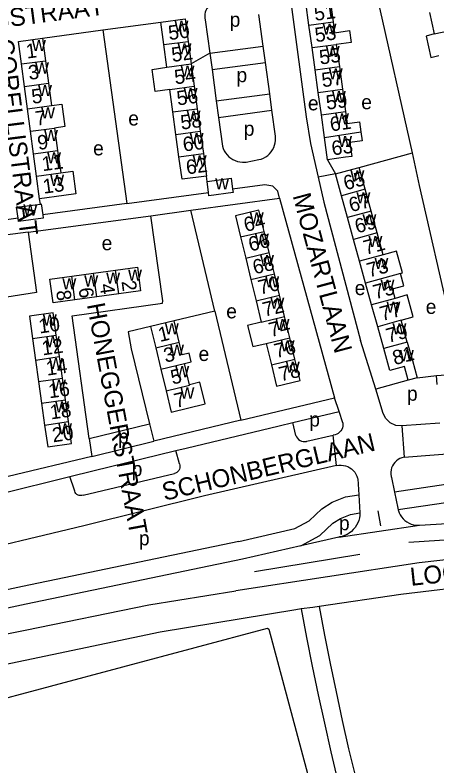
# Model space of a CAD drawing. Extents: x 159045 to 160918, y 380454 to 382516.
# Drawn here: x 159624.4 to 159741.6, y 380775.4 to 380983.9 of the extents above; entities that cross this region are included whole.
import ezdxf

# ---------------------------------------------------------------- set-up
doc = ezdxf.new("R2010")
doc.units = 0
for name, color, linetype in [('BLT_Basislijn', 7, 'Continuous'), ('BLT_Bebouwing', 7, 'Continuous'), ('BLT_Centroide', 7, 'Continuous'), ('BLT_Huisnummer', 7, 'Continuous'), ('BLT_Huisnummer_ tussenligend', 7, 'Continuous'), ('BLT_Onderverdeling_panden', 7, 'Continuous'), ('BLT_Straatnaam', 7, 'Continuous'), ('BLT_Vlakafsluiter', 7, 'Continuous')]:
    doc.layers.add(name, color=color, linetype=linetype)

msp = doc.modelspace()

# ---------------------------------------------------------------- linework, layer by layer
at = {"layer": 'BLT_Basislijn'}
for p, q in [((159734.78, 380945.62), (159724.83, 380989.95)), ((159677.16, 380983.06), (159677.26, 380982.6)), ((159677.26, 380982.6), (159678.52, 380973.28)), ((159693.34, 380975.29), (159692.16, 380984.04)), ((159648.82, 380979.77), (159664.91, 380981.9)), ((159632.05, 380977.44), (159648.82, 380979.77)), ((159648.82, 380979.77), (159655.51, 380931.55)), ((159678.52, 380973.28), (159693.34, 380975.29)), ((159693.96, 380970.71), (159693.34, 380975.29)), ((159678.52, 380973.28), (159679.13, 380968.73)), ((159679.13, 380968.73), (159693.96, 380970.71)), ((159695.14, 380962.01), (159693.96, 380970.71)), ((159679.13, 380968.73), (159680.31, 380960.03)), ((159680.31, 380960.03), (159695.14, 380962.01)), ((159695.76, 380957.46), (159695.14, 380962.01)), ((159680.31, 380960.03), (159680.92, 380955.46)), ((159680.92, 380955.46), (159695.76, 380957.46)), ((159696.74, 380950.23), (159695.76, 380957.46)), ((159680.92, 380955.46), (159682, 380947.49)), ((159720, 380941.58), (159734.78, 380945.62)), ((159688.58, 380943.07), (159692.12, 380943.74)), ((159711.21, 380943.7), (159713.44, 380939.77)), ((159677.73, 380937.68), (159677.55, 380939.2)), ((159713.44, 380939.77), (159708.58, 380938.84)), ((159655.51, 380931.55), (159678.14, 380934.62)), ((159631.45, 380931.41), (159631.25, 380932.91)), ((159673.28, 380929.68), (159697.9, 380933.09)), ((159697.9, 380933.09), (159713.14, 380877.64)), ((159655.51, 380931.55), (159632.11, 380928.38)), ((159662.16, 380928.16), (159673.28, 380929.68)), ((159679.91, 380901.66), (159673.28, 380929.68)), ((159625.26, 380927.46), (159612.94, 380925.8)), ((159628.06, 380923.63), (159662.16, 380928.16)), ((159628.06, 380923.63), (159599.52, 380919.83)), ((159679.91, 380901.66), (159668.57, 380899.01)), ((159679.91, 380901.66), (159687.1, 380871.43)), ((159724.57, 380879.99), (159720.34, 380893.51)), ((159733.63, 380882.49), (159724.57, 380879.99)), ((159736.08, 380883.17), (159741.42, 380883.85)), ((159726.66, 380873.3), (159724.57, 380879.99)), ((159687.1, 380871.43), (159713.14, 380877.64)), ((159714.4, 380873.83), (159713.14, 380877.64)), ((159701.52, 380870.76), (159714.4, 380873.83)), ((159715.44, 380870.7), (159714.4, 380873.83)), ((159645.03, 380866.31), (159661.78, 380870.42)), ((159661.78, 380870.42), (159662.96, 380865.57)), ((159687.1, 380871.43), (159662.96, 380865.57)), ((159702.39, 380867.16), (159701.52, 380870.76)), ((159742.35, 380870.62), (159731.82, 380869.8)), ((159645.03, 380866.31), (159645.71, 380861.33)), ((159705.48, 380865.55), (159712.8, 380867.27)), ((159645.71, 380861.33), (159662.96, 380865.57)), ((159670.06, 380859.28), (159669.06, 380862.95)), ((159645.71, 380861.33), (159622.53, 380855.79)), ((159640.96, 380852), (159639.62, 380855.76)), ((159643.32, 380850.61), (159668.66, 380856.63)), ((159728.94, 380855.47), (159729.78, 380851.4)), ((159719.6, 380855.12), (159719.88, 380850.69)), ((159729.78, 380851.4), (159730.69, 380847.02)), ((159719.88, 380850.69), (159720.19, 380845.67)), ((159725.19, 380846.25), (159725.88, 380842.09)), ((159630.36, 380838.96), (159596.82, 380830.73)), ((159714.32, 380838.96), (159703.75, 380836.52)), ((159733.79, 380837.57), (159763.63, 380839.43)), ((159703.75, 380836.52), (159687.61, 380832.79)), ((159690.9, 380829.36), (159720.18, 380834.21)), ((159703.92, 380818.98), (159702.38, 380818.76)), ((159707.16, 380819.44), (159703.92, 380818.98)), ((159708.87, 380819.68), (159707.16, 380819.44))]:
    msp.add_line(p, q, dxfattribs=at)
for points in [[(159679.86, 380987.36), (159679.34, 380987.16), (159678.85, 380986.88), (159678.41, 380986.54), (159678.02, 380986.14), (159677.7, 380985.69), (159677.44, 380985.2), (159677.25, 380984.68), (159677.15, 380984.13), (159677.12, 380983.58), (159677.16, 380983.06)], [(159705.16, 380987.36), (159701.3, 380987.08), (159701.09, 380986.78), (159705.25, 380955.64), (159706.44, 380948.27), (159708.58, 380938.84)], [(159692.12, 380943.74), (159692.78, 380943.92), (159693.42, 380944.18), (159694.02, 380944.52), (159694.58, 380944.92), (159695.09, 380945.39), (159695.54, 380945.91), (159695.93, 380946.47), (159696.25, 380947.08), (159696.5, 380947.73), (159696.67, 380948.39), (159696.76, 380949.08), (159696.78, 380949.77), (159696.74, 380950.23)], [(159682, 380947.49), (159682.22, 380946.83), (159682.51, 380946.2), (159682.87, 380945.61), (159683.3, 380945.06), (159683.79, 380944.57), (159684.33, 380944.13), (159684.92, 380943.77), (159685.55, 380943.47), (159686.21, 380943.24), (159686.88, 380943.1), (159687.58, 380943.03), (159688.27, 380943.04), (159688.58, 380943.07)], [(159757.79, 380900.82), (159746.59, 380898.96), (159745.36, 380898.99), (159736.77, 380936.61), (159734.78, 380945.62)], [(159708.58, 380938.84), (159710.15, 380931.92), (159720.34, 380893.51)], [(159697.9, 380933.09), (159697.38, 380934.95), (159696, 380936.42), (159693.83, 380936.74), (159684.83, 380935.52)], [(159645.03, 380866.31), (159640.33, 380900.36), (159665.35, 380903.89), (159665.46, 380904.55), (159662.16, 380928.16)], [(159628.06, 380923.63), (159630.34, 380906.88), (159615.55, 380904.57), (159616.91, 380894.64)], [(159662.06, 380897.44), (159655.86, 380895.9), (159656.7, 380891.22), (159661.78, 380870.42)], [(159731.82, 380869.8), (159730.2, 380869.94), (159728.63, 380870.65), (159727.39, 380871.84), (159726.66, 380873.3)], [(159669.06, 380862.95), (159671.9, 380863.65), (159697.77, 380869.87), (159701.52, 380870.76)], [(159715.44, 380870.7), (159715.48, 380870.22), (159715.45, 380869.74), (159715.33, 380869.26), (159715.14, 380868.82), (159714.87, 380868.41), (159714.55, 380868.05), (159714.17, 380867.75), (159713.74, 380867.52), (159713.28, 380867.35), (159712.8, 380867.27)], [(159702.39, 380867.16), (159702.59, 380866.75), (159702.85, 380866.38), (159703.18, 380866.06), (159703.56, 380865.8), (159703.97, 380865.61), (159704.41, 380865.5), (159704.87, 380865.47), (159705.32, 380865.51), (159705.48, 380865.55)], [(159732.45, 380861.14), (159749.17, 380862.42), (159809.36, 380866.58)], [(159639.62, 380855.76), (159646.05, 380857.34), (159669.06, 380862.95)], [(159732.45, 380861.14), (159731.87, 380860.99), (159731.32, 380860.77), (159730.8, 380860.48), (159730.32, 380860.12), (159729.89, 380859.7), (159729.52, 380859.23), (159729.23, 380858.71), (159729, 380858.16), (159728.84, 380857.58), (159728.77, 380856.99), (159728.77, 380856.39), (159728.86, 380855.8), (159728.94, 380855.47)], [(159713.73, 380858.79), (159677.04, 380850.42), (159643.57, 380842.04), (159630.36, 380838.96)], [(159670.06, 380859.28), (159670.18, 380858.91), (159670.22, 380858.52), (159670.19, 380858.13), (159670.07, 380857.76), (159669.88, 380857.42), (159669.63, 380857.12), (159669.32, 380856.88), (159668.97, 380856.71), (159668.66, 380856.63)], [(159713.73, 380858.79), (159714.35, 380858.89), (159714.97, 380858.91), (159715.6, 380858.85), (159716.21, 380858.72), (159716.8, 380858.5), (159717.35, 380858.22), (159717.87, 380857.86), (159718.33, 380857.44), (159718.74, 380856.97), (159719.08, 380856.45), (159719.36, 380855.88), (159719.56, 380855.29), (159719.6, 380855.12)], [(159607.49, 380847.78), (159620.22, 380850.96), (159639.62, 380855.76)], [(159760.2, 380848.71), (159754.66, 380850.03), (159748.12, 380852.85), (159744.08, 380853.51), (159729.78, 380851.4)], [(159643.32, 380850.61), (159642.97, 380850.49), (159642.61, 380850.45), (159642.25, 380850.49), (159641.91, 380850.61), (159641.6, 380850.8), (159641.34, 380851.06), (159641.14, 380851.36), (159641.01, 380851.7), (159640.96, 380852)], [(159686.59, 380837.69), (159702.08, 380841.3), (159706.09, 380843.47), (159709.59, 380846.83), (159712.52, 380848.63), (159716.21, 380850.1), (159719.88, 380850.69)], [(159759.77, 380843.67), (159753.07, 380845.27), (159746.71, 380848.01), (159744.04, 380848.45), (159730.81, 380846.5)], [(159703.75, 380836.52), (159709.07, 380839.4), (159712.67, 380842.85), (159714.77, 380844.14), (159717.54, 380845.25), (159720.19, 380845.67)], [(159720.19, 380845.67), (159720.16, 380844.98), (159720.04, 380844.25), (159719.85, 380843.54), (159719.58, 380842.86), (159719.24, 380842.21), (159718.83, 380841.6), (159718.36, 380841.04), (159717.83, 380840.53), (159717.24, 380840.08), (159716.62, 380839.7), (159715.95, 380839.39), (159715.25, 380839.15), (159714.54, 380838.99), (159714.32, 380838.96)], [(159730.69, 380847.02), (159730.81, 380846.5)], [(159730.81, 380846.5), (159731.08, 380845.72), (159731.38, 380845.11), (159731.76, 380844.54), (159732.19, 380844.02), (159732.69, 380843.55), (159733.24, 380843.15), (159733.83, 380842.82), (159734.45, 380842.55), (159735.11, 380842.36), (159735.78, 380842.25), (159736.46, 380842.22), (159736.78, 380842.23)], [(159736.78, 380842.23), (159759.77, 380843.67)], [(159686.59, 380837.69), (159626.47, 380825.2), (159588, 380816.97)], [(159796.37, 380838.55), (159736.61, 380831.78), (159685.69, 380824.02)], [(159687.61, 380832.79), (159627.5, 380820.3), (159589.04, 380812.08)], [(159785.88, 380829.46), (159784.03, 380829.26), (159777.98, 380828.55), (159731.58, 380822.97), (159708.87, 380819.68)], [(159574.18, 380802.53), (159627.2, 380813.1), (159661.54, 380820.15), (159685.69, 380824.02)], [(159702.38, 380818.76), (159664.72, 380812.51), (159550.45, 380788.58)], [(159703.92, 380818.98), (159705.4, 380811.02), (159706.96, 380803.08), (159708.6, 380795.16), (159710.32, 380787.25), (159712.12, 380779.36), (159713.99, 380771.49), (159715.94, 380763.64), (159717.97, 380755.8), (159720.08, 380747.99), (159722.26, 380740.2), (159724.52, 380732.43), (159726.86, 380724.68), (159729.28, 380716.96), (159731.77, 380709.26), (159734.34, 380701.59), (159736.98, 380693.94), (159739.7, 380686.32), (159741.35, 380681.79)], [(159708.87, 380819.68), (159710.35, 380811.75), (159711.91, 380803.84), (159713.55, 380795.94), (159715.26, 380788.06), (159717.06, 380780.19), (159718.93, 380772.35), (159720.88, 380764.52), (159722.91, 380756.71), (159725.01, 380748.92), (159727.19, 380741.16), (159729.45, 380733.41), (159731.79, 380725.69), (159734.2, 380717.99), (159736.68, 380710.32), (159739.25, 380702.67), (159741.89, 380695.05), (159744.6, 380687.45), (159745.66, 380684.56)], [(159553.84, 380776.05), (159694.54, 380813.62), (159694.88, 380813.4), (159722.55, 380710.08), (159722.69, 380708.76), (159585.61, 380671.57)]]:
    msp.add_lwpolyline(points, dxfattribs=at)
at = {"layer": 'BLT_Bebouwing'}
for p, q in [((159706.03, 380981.12), (159705.16, 380987.36)), ((159739.52, 380984.62), (159740.83, 380978.64)), ((159665.75, 380975.67), (159664.91, 380981.9)), ((159706.89, 380974.88), (159706.03, 380981.12)), ((159632.05, 380977.44), (159632.89, 380971.21)), ((159672.51, 380976.58), (159673.35, 380970.35)), ((159666.59, 380969.44), (159665.75, 380975.67)), ((159707.76, 380968.65), (159706.89, 380974.88)), ((159627.04, 380964.07), (159626.2, 380970.31)), ((159632.89, 380971.21), (159633.73, 380964.98)), ((159673.35, 380970.35), (159674.19, 380964.12)), ((159708.62, 380962.41), (159707.76, 380968.65)), ((159714.49, 380969.58), (159715.36, 380963.34)), ((159627.88, 380957.84), (159627.04, 380964.07)), ((159633.73, 380964.98), (159634.57, 380958.74)), ((159674.19, 380964.12), (159675.03, 380957.89)), ((159668.27, 380956.98), (159667.43, 380963.21)), ((159709.49, 380956.17), (159708.62, 380962.41)), ((159715.36, 380963.34), (159716.22, 380957.11)), ((159628.72, 380951.61), (159627.88, 380957.84)), ((159675.03, 380957.89), (159675.87, 380951.66)), ((159669.11, 380950.75), (159668.27, 380956.98)), ((159710.35, 380949.93), (159709.49, 380956.17)), ((159629.56, 380945.37), (159628.72, 380951.61)), ((159635.41, 380952.51), (159636.25, 380946.28)), ((159675.87, 380951.66), (159676.71, 380945.43)), ((159669.95, 380944.52), (159669.11, 380950.75)), ((159711.21, 380943.7), (159710.35, 380949.93)), ((159630.4, 380939.14), (159629.56, 380945.37)), ((159636.25, 380946.28), (159637.1, 380940.04)), ((159676.71, 380945.43), (159677.55, 380939.2)), ((159721.67, 380935.51), (159720, 380941.58)), ((159631.25, 380932.91), (159630.4, 380939.14)), ((159715.11, 380933.71), (159713.44, 380939.77)), ((159678.14, 380934.62), (159677.73, 380937.68)), ((159723.34, 380929.45), (159721.67, 380935.51)), ((159716.77, 380927.64), (159715.11, 380933.71)), ((159725.01, 380923.39), (159723.34, 380929.45)), ((159718.44, 380921.58), (159716.77, 380927.64)), ((159687.06, 380922.27), (159688.49, 380916.35)), ((159695.01, 380917.92), (159693.58, 380923.84)), ((159726.68, 380917.33), (159725.01, 380923.39)), ((159720.11, 380915.52), (159718.44, 380921.58)), ((159688.49, 380916.35), (159689.92, 380910.43)), ((159696.43, 380912), (159695.01, 380917.92)), ((159721.78, 380909.46), (159720.11, 380915.52)), ((159640.16, 380911.4), (159646.24, 380912.23)), ((159646.24, 380912.23), (159652.32, 380913.05)), ((159697.86, 380906.09), (159696.43, 380912)), ((159689.92, 380910.43), (159691.35, 380904.51)), ((159723.45, 380903.4), (159721.78, 380909.46)), ((159647.13, 380905.63), (159641.05, 380904.8)), ((159653.22, 380906.45), (159647.13, 380905.63)), ((159699.29, 380900.17), (159697.86, 380906.09)), ((159641.05, 380904.8), (159634.97, 380903.98)), ((159691.35, 380904.51), (159692.77, 380898.59)), ((159725.12, 380897.34), (159723.45, 380903.4)), ((159635.89, 380895.03), (159635.03, 380901.17)), ((159700.72, 380894.25), (159699.29, 380900.17)), ((159668.57, 380899.01), (159662.06, 380897.44)), ((159662.06, 380897.44), (159663.5, 380891.49)), ((159670, 380893.06), (159668.57, 380899.01)), ((159726.79, 380891.27), (159725.12, 380897.34)), ((159733.35, 380893.08), (159731.68, 380899.14)), ((159636.73, 380889.05), (159635.89, 380895.03)), ((159702.15, 380888.33), (159700.72, 380894.25)), ((159663.5, 380891.49), (159664.94, 380885.54)), ((159694.2, 380892.67), (159695.63, 380886.76)), ((159728.46, 380885.21), (159726.79, 380891.27)), ((159637.58, 380883.07), (159636.73, 380889.05)), ((159630.11, 380888.11), (159630.95, 380882.13)), ((159672.86, 380881.24), (159671.44, 380887.11)), ((159664.94, 380885.54), (159666.37, 380879.59)), ((159638.43, 380877.03), (159637.58, 380883.07)), ((159630.95, 380882.13), (159631.8, 380876.1)), ((159639.28, 380871), (159638.43, 380877.03)), ((159631.8, 380876.1), (159632.65, 380870.06))]:
    msp.add_line(p, q, dxfattribs=at)
for points in [[(159711.9, 380988.29), (159712.59, 380983.34), (159712.76, 380982.05)], [(159664.91, 380981.9), (159671.67, 380982.82), (159672.51, 380976.58)], [(159712.76, 380982.05), (159713.17, 380979), (159717.27, 380979.57), (159717.73, 380976.31), (159713.64, 380975.75)], [(159740.83, 380978.64), (159738.61, 380978.05), (159739.9, 380972.08), (159742.13, 380972.65)], [(159626.2, 380970.31), (159625.36, 380976.54), (159632.05, 380977.44)], [(159713.64, 380975.75), (159714.49, 380969.58)], [(159667.43, 380963.21), (159663.36, 380962.71), (159662.53, 380968.82), (159666.59, 380969.44)], [(159634.57, 380958.74), (159637.43, 380959.11), (159638.26, 380952.92), (159635.41, 380952.51)], [(159716.22, 380957.11), (159716.69, 380953.74), (159720.07, 380954.25), (159720.45, 380951.44)], [(159720.45, 380951.44), (159720.79, 380948.99), (159717.41, 380948.53), (159717.95, 380944.63), (159716.17, 380944.39), (159711.21, 380943.7)], [(159677.55, 380939.2), (159670.8, 380938.29), (159669.95, 380944.52)], [(159713.44, 380939.77), (159718.26, 380941.1), (159720, 380941.58)], [(159637.1, 380940.04), (159640.46, 380940.51), (159641.3, 380934.26), (159637.94, 380933.81), (159631.25, 380932.91)], [(159677.73, 380937.68), (159684.41, 380938.59), (159684.83, 380935.52)], [(159684.83, 380935.52), (159684.95, 380934.6), (159678.27, 380933.69), (159678.14, 380934.62)], [(159625.26, 380927.46), (159624.85, 380930.52), (159631.45, 380931.41)], [(159631.45, 380931.41), (159631.69, 380931.45), (159632.11, 380928.38)], [(159632.11, 380928.38), (159632.23, 380927.47), (159625.39, 380926.54), (159625.26, 380927.46)], [(159693.58, 380923.84), (159692.15, 380929.76), (159685.63, 380928.19), (159687.06, 380922.27)], [(159731.49, 380912.15), (159732.02, 380912.29), (159730.36, 380918.32), (159726.68, 380917.33)], [(159652.32, 380913.05), (159658.4, 380913.88), (159659.3, 380907.28), (159653.22, 380906.45)], [(159730.02, 380905.21), (159729.28, 380907.88), (159732.43, 380908.74), (159731.49, 380912.15)], [(159634.97, 380903.98), (159634.08, 380910.58), (159640.16, 380911.4)], [(159731.68, 380899.14), (159735, 380900.14), (159733.34, 380906.17), (159730.02, 380905.21)], [(159635.03, 380901.17), (159628.4, 380900.24), (159629.27, 380894.1)], [(159692.77, 380898.59), (159688.99, 380897.71), (159690.41, 380891.83), (159694.2, 380892.67)], [(159629.27, 380894.1), (159630.11, 380888.11)], [(159671.44, 380887.11), (159673.33, 380887.57), (159672.73, 380890.05), (159670.84, 380889.58), (159670, 380893.06)], [(159733.35, 380893.08), (159734.76, 380887.99), (159736.08, 380883.17)], [(159695.63, 380886.76), (159697.06, 380880.83), (159703.58, 380882.4), (159702.15, 380888.33)], [(159733.63, 380882.49), (159732.57, 380886.35), (159728.46, 380885.21)], [(159741.42, 380883.85), (159751.71, 380884.58)], [(159736.08, 380883.17), (159733.63, 380882.49)], [(159741.6, 380881.27), (159741.42, 380883.85)], [(159666.37, 380879.59), (159667.81, 380873.64), (159677.18, 380875.9), (159675.78, 380881.93), (159672.86, 380881.24)], [(159632.65, 380870.06), (159633.5, 380864.03), (159640.13, 380864.96), (159639.28, 380871)]]:
    msp.add_lwpolyline(points, dxfattribs=at)
at = {"layer": 'BLT_Onderverdeling_panden'}
for p, q in [((159706.03, 380981.12), (159712.76, 380982.05)), ((159740.83, 380978.64), (159747.99, 380980.2)), ((159665.75, 380975.67), (159672.51, 380976.58)), ((159706.89, 380974.88), (159713.64, 380975.75)), ((159626.2, 380970.31), (159632.89, 380971.21)), ((159666.59, 380969.44), (159673.35, 380970.35)), ((159707.76, 380968.65), (159714.49, 380969.58)), ((159627.04, 380964.07), (159633.73, 380964.98)), ((159667.43, 380963.21), (159674.19, 380964.12)), ((159708.62, 380962.41), (159715.36, 380963.34)), ((159627.88, 380957.84), (159634.57, 380958.74)), ((159668.27, 380956.98), (159675.03, 380957.89)), ((159709.49, 380956.17), (159716.22, 380957.11)), ((159628.72, 380951.61), (159635.41, 380952.51)), ((159669.11, 380950.75), (159675.87, 380951.66)), ((159710.35, 380949.93), (159720.45, 380951.44)), ((159629.56, 380945.37), (159636.25, 380946.28)), ((159669.95, 380944.52), (159676.71, 380945.43)), ((159630.4, 380939.14), (159637.1, 380940.04)), ((159721.67, 380935.51), (159715.11, 380933.71)), ((159723.34, 380929.45), (159716.77, 380927.64)), ((159687.06, 380922.27), (159693.58, 380923.84)), ((159725.01, 380923.39), (159718.44, 380921.58)), ((159688.49, 380916.35), (159695.01, 380917.92)), ((159726.68, 380917.33), (159720.11, 380915.52)), ((159647.13, 380905.63), (159646.24, 380912.23)), ((159653.22, 380906.45), (159652.32, 380913.05)), ((159689.92, 380910.43), (159696.43, 380912)), ((159731.49, 380912.15), (159721.78, 380909.46)), ((159641.05, 380904.8), (159640.16, 380911.4)), ((159691.35, 380904.51), (159697.86, 380906.09)), ((159730.02, 380905.21), (159723.45, 380903.4)), ((159692.77, 380898.59), (159699.29, 380900.17)), ((159731.68, 380899.14), (159725.12, 380897.34)), ((159629.27, 380894.1), (159635.89, 380895.03)), ((159663.5, 380891.49), (159670, 380893.06)), ((159694.2, 380892.67), (159700.72, 380894.25)), ((159733.35, 380893.08), (159726.79, 380891.27)), ((159630.11, 380888.11), (159636.73, 380889.05)), ((159664.94, 380885.54), (159671.44, 380887.11)), ((159695.63, 380886.76), (159702.15, 380888.33)), ((159630.95, 380882.13), (159637.58, 380883.07)), ((159631.8, 380876.1), (159638.43, 380877.03)), ((159632.65, 380870.06), (159639.28, 380871))]:
    msp.add_line(p, q, dxfattribs=at)
msp.add_lwpolyline([(159666.37, 380879.59), (159672.88, 380881.16), (159672.86, 380881.24)], dxfattribs=at)
at = {"layer": 'BLT_Vlakafsluiter'}
for p, q in [((159678.52, 380973.28), (159673.35, 380970.35)), ((159731.82, 380869.8), (159732.45, 380861.14)), ((159713.73, 380858.79), (159712.8, 380867.27)), ((159714.32, 380838.96), (159736.78, 380842.23))]:
    msp.add_line(p, q, dxfattribs=at)

# ---------------------------------------------------------------- texts
at = {"layer": 'BLT_Centroide'}
for s, p in [('p', (159684.01, 380980.64)), ('w', (159668.7, 380979.25)), ('w', (159709.83, 380978.47)), ('w', (159629.12, 380973.88)), ('w', (159669.55, 380973)), ('w', (159710.7, 380972.22)), ('w', (159629.97, 380967.66)), ('w', (159670.39, 380966.78)), ('p', (159685.91, 380965.25)), ('w', (159711.55, 380966)), ('w', (159630.81, 380961.41)), ('w', (159671.23, 380960.56)), ('w', (159712.42, 380959.75)), ('e', (159705.75, 380957.43)), ('e', (159720.56, 380957.74)), ('w', (159631.64, 380955.19)), ('e', (159655.86, 380953.22)), ('w', (159672.07, 380954.31)), ('w', (159713.29, 380953.53)), ('p', (159687.93, 380950.37)), ('w', (159632.48, 380948.94)), ('w', (159672.91, 380948.09)), ('w', (159714.15, 380947.28)), ('e', (159646.1, 380944.93)), ('w', (159633.33, 380942.72)), ('w', (159673.75, 380941.84)), ('w', (159634.17, 380936.47)), ('w', (159717.55, 380937.66)), ('w', (159679.99, 380935.48)), ('w', (159719.22, 380931.59)), ('w', (159626.73, 380928.23)), ('w', (159689.6, 380926)), ('w', (159720.89, 380925.53)), ('w', (159691.03, 380920.09)), ('w', (159722.56, 380919.47)), ('e', (159648.47, 380918.6)), ('w', (159692.46, 380914.19)), ('w', (159724.23, 380913.41)), ('w', (159649.73, 380909.33)), ('w', (159655.81, 380910.17)), ('w', (159637.56, 380907.69)), ('w', (159643.64, 380908.52)), ('w', (159693.89, 380908.25)), ('w', (159725.9, 380907.34)), ('e', (159718.74, 380906.14)), ('w', (159695.32, 380902.34)), ('w', (159727.56, 380901.28)), ('e', (159738.47, 380900.92)), ('e', (159683.06, 380899.67)), ('w', (159632.14, 380897.69)), ('w', (159696.75, 380896.41)), ('w', (159666.03, 380895.25)), ('w', (159729.23, 380895.22)), ('w', (159632.98, 380891.66)), ('w', (159698.18, 380890.5)), ('w', (159667.47, 380889.31)), ('e', (159675.38, 380887.84)), ('w', (159731.28, 380887.78)), ('w', (159633.84, 380885.62)), ('w', (159699.61, 380884.59)), ('w', (159668.91, 380883.34)), ('w', (159634.69, 380879.59)), ('w', (159670.34, 380877.41)), ('p', (159733.25, 380876.81)), ('w', (159635.54, 380873.56)), ('p', (159706.11, 380869.64)), ('w', (159636.39, 380867.5)), ('p', (159653.02, 380864.89)), ('p', (159656.82, 380855.88)), ('p', (159714.37, 380840.83)), ('p', (159658.82, 380836.65))]:
    msp.add_text(s, height=4, dxfattribs=at).set_placement(p)
at = {"layer": 'BLT_Huisnummer'}
for s, rotation, p in [('51', 7.8942, (159707.74, 380982.26)), ('50', 7.6857, (159667.24, 380976.92)), ('1', 7.6872, (159627.72, 380971.79)), ('55', 7.8953, (159709.18, 380970.13)), ('54', 7.6879, (159668.93, 380964.63)), ('5', 7.6883, (159629.25, 380959.23)), ('59', 7.8953, (159711.04, 380957.58)), ('58', 7.6902, (159670.63, 380952.05)), ('9', 7.6895, (159630.9, 380946.43)), ('63', 7.8968, (159712.59, 380944.89)), ('62', 7.6857, (159672.17, 380939.62)), ('13', 7.686, (159632.41, 380934.27)), ('65', 15.3931, (159716.23, 380935.2)), ('64', 13.5742, (159688.46, 380923.64)), ('69', 15.3931, (159719.4, 380923.22)), ('68', 13.5679, (159690.95, 380911.87)), ('73', 15.3931, (159722.73, 380910.99)), ('2', 277.7334, (159653.98, 380909.95)), ('8', 277.7237, (159635.82, 380907.28)), ('72', 13.5699, (159693.68, 380900.09)), ('77', 15.3931, (159726.33, 380898.9)), ('10', 8.0163, (159631.23, 380895.46)), ('1', 13.571, (159664.68, 380893.09)), ('81', 15.3976, (159729.86, 380886.66)), ('14', 8.0186, (159633.29, 380883.76)), ('78', 13.5679, (159698.21, 380882.14)), ('7', 13.571, (159669.12, 380874.77)), ('20', 8.0151, (159635.01, 380865.24))]:
    msp.add_text(s, height=4, rotation=rotation, dxfattribs=at).set_placement(p)
at = {"layer": 'BLT_Huisnummer_ tussenligend'}
for s, rotation, p in [('53', 7.8942, (159707.94, 380976.34)), ('52', 7.6857, (159668.12, 380970.85)), ('3', 7.6872, (159628.36, 380965.87)), ('57', 7.8953, (159709.82, 380963.83)), ('56', 7.6879, (159669.58, 380958.77)), ('7', 7.6883, (159630.32, 380953.15)), ('61', 7.8953, (159712.14, 380951.56)), ('60', 7.6902, (159671.27, 380945.97)), ('11', 7.6895, (159632.12, 380940.53)), ('67', 15.3931, (159717.74, 380929.12)), ('66', 13.5742, (159689.76, 380918.21)), ('71', 15.3931, (159721.8, 380917.26)), ('70', 13.5679, (159692.46, 380906.23)), ('75', 15.3931, (159724.46, 380904.92)), ('6', 277.7334, (159642.06, 380908.01)), ('4', 277.7334, (159647.91, 380909.09)), ('74', 13.5699, (159695.4, 380894.44)), ('79', 15.3931, (159728.08, 380892.82)), ('12', 8.0163, (159632.11, 380889.38)), ('76', 13.5699, (159696.92, 380888.59)), ('3', 13.571, (159666.2, 380887.34)), ('5', 13.571, (159668.15, 380881.26)), ('16', 8.0186, (159633.95, 380877.46)), ('18', 8.0186, (159634.39, 380871.6))]:
    msp.add_text(s, height=4, rotation=rotation, dxfattribs=at).set_placement(p)
at = {"layer": 'BLT_Straatnaam'}
for s, height, rotation, p in [('VAN BLANKENBURGSTRAAT', 5, 7.4255, (159557.63, 380972.09)), ('CORELLISTRAAT', 5, 277.1911, (159619, 380976.98)), ('MOZARTLAAN', 5, 284.9965, (159701.48, 380933.74)), ('HONEGGERSTRAAT', 5, 280.5888, (159644.36, 380903.52)), ('SCHONBERGLAAN', 5, 13.4342, (159665.91, 380848.99)), ('LOCATELLISTRAAT', 4.9999, 5.9978, (159734.37, 380825.4))]:
    msp.add_text(s, height=height, rotation=rotation, dxfattribs=at).set_placement(p)

doc.saveas('drawing.dxf')
